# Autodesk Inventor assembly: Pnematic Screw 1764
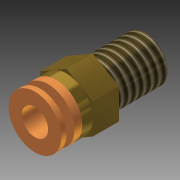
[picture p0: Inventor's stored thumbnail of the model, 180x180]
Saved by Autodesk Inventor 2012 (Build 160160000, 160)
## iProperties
Created: 2010-02
Part Number: Pnematic Screw 1764
Document SubType Name: Assembly
Designer: clee1
Author: clee1
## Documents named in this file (3)
- R:\CAD Archives\Pneumatics_1764\Air_Release_1764\Pneumatic_Screw_1764\Pneumatic_Screw_1764.iam
- R:\CAD Archives\Pneumatics_1764\Air_Release_1764\Pneumatic_Screw_1764\Pneumatic_Screw_Part_1_1764.ipt
- R:\CAD Archives\Pneumatics_1764\Air_Release_1764\Pneumatic_Screw_1764\Pneumatic_Screw_Part_2_1764.ipt
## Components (2 placed, 2 different names)
1. Pneumatic_Screw_Part_1_1764:1 — Insert:1
2. Pneumatic_Screw_Part_2_1764:1 — Insert:1
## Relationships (1: Insert 1)
- Insert:1: Pneumatic_Screw_Part_1_1764:1 ↔ Pneumatic_Screw_Part_2_1764:1
